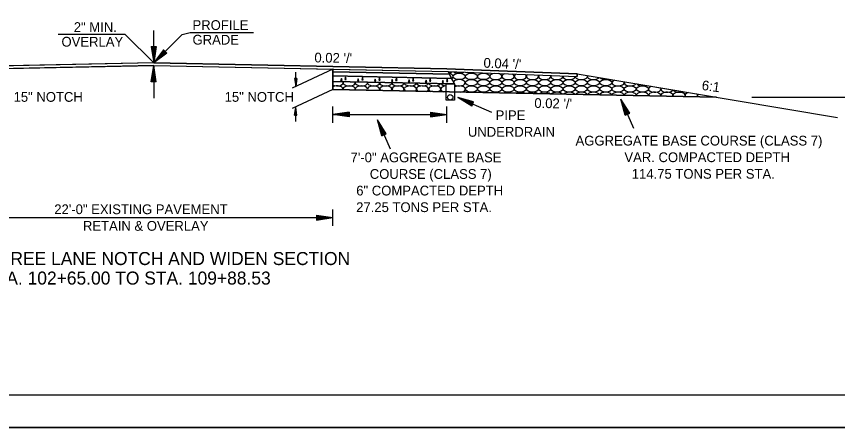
# Model space of a CAD drawing. Extents: x 1371763 to 1372860, y 385599 to 385872.
# Drawn here: x 1372352.1 to 1372402.6, y 385598.6 to 385623.8 of the extents above; entities that cross this region are included whole.
import ezdxf

# ---------------------------------------------------------------- set-up
doc = ezdxf.new("R2010")
doc.units = 0
for name, color, linetype in [('R_Border', 7, 'Continuous'), ('R_Draft', 7, 'Continuous'), ('R_No Plot', 7, 'Continuous')]:
    doc.layers.add(name, color=color, linetype=linetype)

msp = doc.modelspace()

# ---------------------------------------------------------------- linework, layer by layer
at = {"layer": 'R_Border'}
msp.add_line((1372457.298, 385600.577), (1372299.208, 385600.577), dxfattribs=at)
at = {"layer": 'R_Draft'}
for p, q in [((1372358.829, 385622.739), (1372354.703, 385622.739)), ((1372360.579, 385620.989), (1372358.829, 385622.739)), ((1372360.579, 385620.989), (1372360.579, 385622.989)), ((1372360.579, 385620.989), (1372362.329, 385622.739)), ((1372362.329, 385622.739), (1372362.829, 385622.864)), ((1372362.829, 385622.864), (1372366.715, 385622.864)), ((1372360.429, 385621.989), (1372360.579, 385620.989)), ((1372360.429, 385621.989), (1372360.729, 385621.989)), ((1372360.454, 385621.989), (1372360.579, 385621.156)), ((1372360.48, 385621.989), (1372360.579, 385621.328)), ((1372360.505, 385621.989), (1372360.579, 385621.494)), ((1372360.531, 385621.989), (1372360.579, 385621.664)), ((1372360.556, 385621.989), (1372360.579, 385621.831)), ((1372360.729, 385621.989), (1372360.579, 385620.989)), ((1372360.628, 385621.989), (1372360.579, 385621.664)), ((1372360.679, 385621.989), (1372360.579, 385621.328)), ((1372360.704, 385621.989), (1372360.579, 385621.156)), ((1372360.654, 385621.989), (1372360.579, 385621.494)), ((1372360.603, 385621.989), (1372360.579, 385621.831)), ((1372361.18, 385621.802), (1372360.579, 385620.989)), ((1372361.198, 385621.784), (1372360.697, 385621.107)), ((1372361.216, 385621.766), (1372360.819, 385621.228)), ((1372361.234, 385621.749), (1372360.937, 385621.346)), ((1372361.252, 385621.731), (1372361.057, 385621.466)), ((1372361.393, 385621.59), (1372361.18, 385621.802)), ((1372361.393, 385621.59), (1372360.579, 385620.989)), ((1372361.375, 385621.608), (1372360.697, 385621.107)), ((1372361.357, 385621.626), (1372360.819, 385621.228)), ((1372361.339, 385621.643), (1372360.937, 385621.346)), ((1372361.321, 385621.662), (1372361.057, 385621.466)), ((1372361.27, 385621.713), (1372361.175, 385621.584)), ((1372361.303, 385621.679), (1372361.175, 385621.584)), ((1372360.579, 385620.822), (1372342.495, 385620.46)), ((1372360.579, 385620.989), (1372342.579, 385620.629)), ((1372360.429, 385619.822), (1372360.579, 385620.822)), ((1372360.579, 385620.989), (1372378.579, 385620.629)), ((1372360.579, 385620.822), (1372378.664, 385620.46)), ((1372360.729, 385619.822), (1372360.579, 385620.822)), ((1372360.579, 385620.822), (1372360.579, 385618.822)), ((1372360.454, 385619.822), (1372360.579, 385620.655)), ((1372360.48, 385619.822), (1372360.579, 385620.483)), ((1372360.505, 385619.822), (1372360.579, 385620.317)), ((1372360.704, 385619.822), (1372360.579, 385620.655)), ((1372360.679, 385619.822), (1372360.579, 385620.483)), ((1372360.654, 385619.822), (1372360.579, 385620.317)), ((1372371.578, 385620.602), (1372369.091, 385619.43)), ((1372369.303, 385619.53), (1372369.303, 385620.43)), ((1372378.579, 385620.629), (1372386.579, 385620.309)), ((1372378.664, 385620.46), (1372378.748, 385620.292)), ((1372378.664, 385620.46), (1372386.579, 385620.144)), ((1372378.748, 385620.292), (1372378.874, 385620.04)), ((1372386.579, 385620.309), (1372402.579, 385617.642)), ((1372386.579, 385620.309), (1372386.579, 385620.144)), ((1372360.729, 385619.822), (1372360.429, 385619.822)), ((1372360.53, 385619.822), (1372360.579, 385620.147)), ((1372360.556, 385619.822), (1372360.579, 385619.98)), ((1372360.628, 385619.822), (1372360.579, 385620.147)), ((1372360.603, 385619.822), (1372360.579, 385619.98)), ((1372369.228, 385620.03), (1372369.303, 385619.53)), ((1372369.378, 385620.03), (1372369.228, 385620.03)), ((1372369.241, 385620.03), (1372369.303, 385619.614)), ((1372369.254, 385620.03), (1372369.303, 385619.7)), ((1372369.266, 385620.03), (1372369.303, 385619.783)), ((1372369.279, 385620.03), (1372369.303, 385619.868)), ((1372369.292, 385620.03), (1372369.303, 385619.951)), ((1372369.378, 385620.03), (1372369.303, 385619.53)), ((1372369.328, 385620.03), (1372369.303, 385619.868)), ((1372369.353, 385620.03), (1372369.303, 385619.7)), ((1372369.366, 385620.03), (1372369.303, 385619.614)), ((1372369.341, 385620.03), (1372369.303, 385619.783)), ((1372369.315, 385620.03), (1372369.303, 385619.951)), ((1372371.579, 385620.185), (1372378.874, 385620.04)), ((1372371.579, 385619.852), (1372379.042, 385619.703)), ((1372378.874, 385620.04), (1372379.042, 385619.703)), ((1372371.579, 385619.352), (1372369.091, 385618.18)), ((1372371.579, 385619.352), (1372395.148, 385618.881)), ((1372379.252, 385618.874), (1372381.318, 385617.964)), ((1372380.106, 385618.334), (1372379.252, 385618.874)), ((1372380.227, 385618.608), (1372379.252, 385618.874)), ((1372380.117, 385618.357), (1372379.404, 385618.806)), ((1372380.217, 385618.585), (1372379.404, 385618.806)), ((1372380.207, 385618.562), (1372379.562, 385618.737)), ((1372380.127, 385618.38), (1372379.562, 385618.737)), ((1372389.273, 385618.754), (1372390.052, 385616.98)), ((1372389.538, 385617.778), (1372389.273, 385618.754)), ((1372389.813, 385617.898), (1372389.273, 385618.754)), ((1372397.317, 385618.881), (1372406.175, 385618.881)), ((1372369.229, 385617.78), (1372369.304, 385618.28)), ((1372369.241, 385617.78), (1372369.304, 385618.197)), ((1372369.379, 385617.78), (1372369.304, 385618.28)), ((1372369.304, 385617.38), (1372369.304, 385618.28)), ((1372369.366, 385617.78), (1372369.304, 385618.197)), ((1372371.579, 385617.317), (1372371.579, 385618.317)), ((1372378.576, 385617.317), (1372378.576, 385618.317)), ((1372380.137, 385618.403), (1372379.714, 385618.67)), ((1372380.197, 385618.539), (1372379.714, 385618.67)), ((1372380.187, 385618.516), (1372379.869, 385618.602)), ((1372380.147, 385618.427), (1372379.869, 385618.602)), ((1372380.176, 385618.493), (1372380.022, 385618.535)), ((1372380.157, 385618.45), (1372380.022, 385618.535)), ((1372380.106, 385618.334), (1372380.227, 385618.608)), ((1372389.561, 385617.788), (1372389.34, 385618.601)), ((1372389.79, 385617.888), (1372389.34, 385618.601)), ((1372389.766, 385617.878), (1372389.41, 385618.443)), ((1372389.584, 385617.798), (1372389.41, 385618.443)), ((1372389.607, 385617.808), (1372389.476, 385618.291)), ((1372389.743, 385617.868), (1372389.476, 385618.291)), ((1372369.229, 385617.78), (1372369.379, 385617.78)), ((1372369.254, 385617.78), (1372369.304, 385618.111)), ((1372369.267, 385617.78), (1372369.304, 385618.028)), ((1372369.28, 385617.78), (1372369.304, 385617.943)), ((1372369.292, 385617.78), (1372369.304, 385617.859)), ((1372369.354, 385617.78), (1372369.304, 385618.111)), ((1372369.341, 385617.78), (1372369.304, 385618.028)), ((1372369.328, 385617.78), (1372369.304, 385617.943)), ((1372369.316, 385617.78), (1372369.304, 385617.859)), ((1372372.579, 385617.967), (1372371.579, 385617.817)), ((1372372.579, 385617.667), (1372371.579, 385617.817)), ((1372371.579, 385617.817), (1372378.576, 385617.817)), ((1372372.579, 385617.942), (1372371.746, 385617.817)), ((1372372.579, 385617.692), (1372371.746, 385617.817)), ((1372372.579, 385617.917), (1372371.918, 385617.817)), ((1372372.579, 385617.718), (1372371.918, 385617.817)), ((1372372.579, 385617.892), (1372372.085, 385617.817)), ((1372372.579, 385617.743), (1372372.085, 385617.817)), ((1372372.579, 385617.866), (1372372.254, 385617.817)), ((1372372.579, 385617.768), (1372372.254, 385617.817)), ((1372372.579, 385617.841), (1372372.421, 385617.817)), ((1372372.579, 385617.794), (1372372.421, 385617.817)), ((1372372.579, 385617.967), (1372372.579, 385617.667)), ((1372377.576, 385617.967), (1372378.576, 385617.817)), ((1372377.576, 385617.967), (1372377.576, 385617.667)), ((1372377.576, 385617.942), (1372378.409, 385617.817)), ((1372377.576, 385617.917), (1372378.237, 385617.817)), ((1372377.576, 385617.892), (1372378.07, 385617.817)), ((1372377.576, 385617.866), (1372377.901, 385617.817)), ((1372377.576, 385617.841), (1372377.734, 385617.817)), ((1372377.576, 385617.667), (1372378.576, 385617.817)), ((1372377.576, 385617.768), (1372377.901, 385617.817)), ((1372377.576, 385617.718), (1372378.237, 385617.817)), ((1372377.576, 385617.692), (1372378.409, 385617.817)), ((1372377.576, 385617.743), (1372378.07, 385617.817)), ((1372377.576, 385617.794), (1372377.734, 385617.817)), ((1372389.538, 385617.778), (1372389.813, 385617.898)), ((1372389.72, 385617.858), (1372389.545, 385618.136)), ((1372389.631, 385617.819), (1372389.545, 385618.136)), ((1372389.697, 385617.848), (1372389.612, 385617.983)), ((1372389.654, 385617.829), (1372389.612, 385617.983)), ((1372374.585, 385616.509), (1372374.32, 385617.485)), ((1372374.86, 385616.629), (1372374.32, 385617.485)), ((1372374.32, 385617.485), (1372375.099, 385615.711)), ((1372374.608, 385616.519), (1372374.387, 385617.332)), ((1372374.837, 385616.619), (1372374.387, 385617.332)), ((1372374.813, 385616.609), (1372374.456, 385617.174)), ((1372374.631, 385616.529), (1372374.456, 385617.174)), ((1372374.654, 385616.539), (1372374.523, 385617.022)), ((1372374.79, 385616.599), (1372374.523, 385617.022)), ((1372374.767, 385616.589), (1372374.592, 385616.867)), ((1372374.678, 385616.55), (1372374.592, 385616.867)), ((1372374.744, 385616.579), (1372374.659, 385616.714)), ((1372374.701, 385616.56), (1372374.659, 385616.714)), ((1372374.585, 385616.509), (1372374.86, 385616.629)), ((1372371.579, 385610.987), (1372371.579, 385611.987)), ((1372349.579, 385611.487), (1372371.579, 385611.487)), ((1372370.579, 385611.637), (1372371.579, 385611.487)), ((1372370.579, 385611.637), (1372370.579, 385611.337)), ((1372370.579, 385611.612), (1372371.412, 385611.487)), ((1372370.579, 385611.586), (1372371.24, 385611.487)), ((1372370.579, 385611.561), (1372371.074, 385611.487)), ((1372370.579, 385611.535), (1372370.904, 385611.487)), ((1372370.579, 385611.51), (1372370.737, 385611.487)), ((1372370.579, 385611.337), (1372371.579, 385611.487)), ((1372370.579, 385611.438), (1372370.904, 385611.487)), ((1372370.579, 385611.387), (1372371.24, 385611.487)), ((1372370.579, 385611.362), (1372371.412, 385611.487)), ((1372370.579, 385611.412), (1372371.074, 385611.487)), ((1372370.579, 385611.463), (1372370.737, 385611.487))]:
    msp.add_line(p, q, dxfattribs=at)
for points in [[(1372360.579, 385620.989), (1372342.579, 385620.629), (1372334.579, 385620.309), (1372334.579, 385620.144), (1372342.495, 385620.46), (1372349.58, 385620.602), (1372360.579, 385620.822), (1372371.578, 385620.602), (1372378.664, 385620.46), (1372386.579, 385620.144), (1372386.579, 385620.309), (1372378.579, 385620.629)], [(1372371.578, 385620.602), (1372378.664, 385620.46), (1372378.748, 385620.292), (1372371.579, 385620.435)], [(1372371.579, 385619.352), (1372371.579, 385619.852), (1372379.042, 385619.703), (1372378.874, 385620.04), (1372378.748, 385620.292), (1372378.664, 385620.46), (1372386.579, 385620.144), (1372386.579, 385620.309), (1372395.148, 385618.881)], [(1372371.579, 385620.185), (1372371.579, 385620.435), (1372378.748, 385620.292), (1372378.874, 385620.04)], [(1372371.579, 385620.185), (1372378.874, 385620.04), (1372379.042, 385619.703), (1372371.579, 385619.852)], [(1372379.042, 385619.703), (1372379.042, 385618.705), (1372378.539, 385618.705), (1372378.539, 385619.703)]]:
    msp.add_lwpolyline(points, close=True, dxfattribs=at)
for points in [[(1372371.578, 385620.602), (1372371.579, 385620.435), (1372371.579, 385620.185), (1372371.579, 385619.852), (1372371.579, 385619.352)], [(1372371.579, 385620.435), (1372378.748, 385620.292)], [(1372372.105, 385620.041), (1372372.057, 385619.908), (1372372.145, 385619.912), (1372372.105, 385620.041)], [(1372372.364, 385620.107), (1372372.316, 385619.974), (1372372.404, 385619.978), (1372372.364, 385620.107)], [(1372373.145, 385620.02), (1372373.096, 385619.887), (1372373.184, 385619.891), (1372373.145, 385620.02)], [(1372373.404, 385620.086), (1372373.355, 385619.953), (1372373.443, 385619.957), (1372373.404, 385620.086)], [(1372374.185, 385619.999), (1372374.136, 385619.867), (1372374.224, 385619.87), (1372374.185, 385619.999)], [(1372374.444, 385620.065), (1372374.395, 385619.933), (1372374.483, 385619.936), (1372374.444, 385620.065)], [(1372375.225, 385619.979), (1372375.176, 385619.846), (1372375.264, 385619.849), (1372375.225, 385619.979)], [(1372375.484, 385620.045), (1372375.435, 385619.912), (1372375.523, 385619.915), (1372375.484, 385620.045)], [(1372376.264, 385619.958), (1372376.216, 385619.825), (1372376.304, 385619.829), (1372376.264, 385619.958)], [(1372376.523, 385620.024), (1372376.475, 385619.891), (1372376.563, 385619.895), (1372376.523, 385620.024)], [(1372377.304, 385619.937), (1372377.256, 385619.804), (1372377.344, 385619.808), (1372377.304, 385619.937)], [(1372377.563, 385620.003), (1372377.515, 385619.87), (1372377.603, 385619.874), (1372377.563, 385620.003)], [(1372378.344, 385619.916), (1372378.296, 385619.783), (1372378.384, 385619.787), (1372378.344, 385619.916)], [(1372378.603, 385619.982), (1372378.555, 385619.849), (1372378.643, 385619.853), (1372378.603, 385619.982)]]:
    msp.add_lwpolyline(points, dxfattribs=at)
msp.add_circle((1372378.791, 385618.872), 0.167, dxfattribs=at)
for centre, start_param, end_param in [((1372378.587, 385620.547), 5.051096, 5.763875), ((1372378.587, 385620.158), 0.74402, 1.197348), ((1372378.587, 385620.158), 5.592596, 7.027205), ((1372379.338, 385620.547), 3.685644, 5.585033), ((1372380.088, 385620.547), 3.891507, 5.37917), ((1372380.838, 385620.547), 4.161511, 5.109166), ((1372381.588, 385620.158), 1.810379, 6.670932), ((1372381.588, 385620.158), 0.387746, 1.177112), ((1372382.339, 385620.158), 2.143322, 6.592146), ((1372382.339, 385620.158), 0.308961, 0.84417), ((1372383.089, 385620.158), 2.366927, 6.51554), ((1372383.089, 385620.158), 0.232354, 0.620564), ((1372383.839, 385620.158), 2.554238, 6.44052), ((1372383.839, 385620.158), 0.157335, 0.433254), ((1372384.589, 385620.158), 2.723473, 6.366593), ((1372386.84, 385620.158), 2.278485, 2.33986), ((1372371.835, 385619.77), 3.96261, 6.65316), ((1372372.585, 385619.77), 2.777136, 6.570444), ((1372373.335, 385619.77), 2.857595, 6.489984), ((1372374.086, 385619.77), 2.936461, 6.411118), ((1372374.836, 385619.77), 3.014293, 6.333287), ((1372375.586, 385619.77), 3.091588, 6.255992), ((1372376.336, 385619.77), 3.168815, 6.178765), ((1372377.087, 385619.77), 3.246438, 6.101142), ((1372377.837, 385619.77), 3.324943, 6.022637), ((1372378.587, 385619.77), 3.404868, 4.583286), ((1372379.338, 385619.77), 3.80645, 9.119957), ((1372385.34, 385620.158), 2.883001, 6.293319), ((1372384.589, 385620.158), 0.083407, 0.264018), ((1372386.09, 385620.158), 3.037942, 6.232735), ((1372385.34, 385620.158), 0.010134, 0.104491), ((1372386.84, 385620.158), 3.19224, 6.523589), ((1372387.59, 385620.158), 2.918865, 5.883208), ((1372388.341, 385620.158), 3.607321, 5.194752), ((1372389.091, 385619.77), 2.199247, 6.602826), ((1372389.841, 385619.77), 2.852988, 5.949086), ((1372371.835, 385619.381), 6.067704, 8.604148), ((1372372.585, 385619.381), 5.988661, 9.642104), ((1372373.335, 385619.381), 5.907944, 9.722821), ((1372374.086, 385619.381), 5.824873, 9.805892), ((1372374.836, 385619.381), 5.738592, 9.892174), ((1372375.586, 385619.381), 5.647958, 9.982807), ((1372376.336, 385619.381), 5.551342, 10.079423), ((1372377.087, 385619.381), 5.446223, 10.184542), ((1372377.837, 385619.381), 5.328222, 10.302543), ((1372378.587, 385619.381), 1.6999, 4.159359), ((1372379.338, 385619.381), 2.178393, 2.476736), ((1372379.338, 385619.381), 4.998472, 8.461578), ((1372382.339, 385618.993), 0.797512, 2.266882), ((1372390.592, 385619.77), 3.518815, 5.283258), ((1372391.342, 385619.381), 2.115117, 6.31057), ((1372391.342, 385618.993), 0.337275, 3.288156), ((1372391.342, 385619.381), 0.027385, 0.403771), ((1372392.092, 385619.381), 2.787209, 6.014865), ((1372392.842, 385619.381), 3.436349, 5.365724), ((1372380.088, 385618.993), 1.301815, 1.762579), ((1372380.838, 385618.993), 1.072981, 1.991414), ((1372381.588, 385618.993), 0.921452, 2.142942), ((1372383.089, 385618.993), 0.688711, 2.375683), ((1372383.839, 385618.993), 0.589594, 2.4748), ((1372384.589, 385618.993), 0.497173, 2.567222), ((1372385.34, 385618.993), 0.409581, 2.654814), ((1372386.09, 385618.993), 0.325542, 2.738853), ((1372386.84, 385618.993), 0.24412, 2.820275), ((1372387.59, 385618.993), 0.164585, 2.89981), ((1372388.341, 385618.993), 0.086335, 2.978059), ((1372389.091, 385618.993), 0.008849, 3.055545), ((1372389.841, 385618.993), 0.853185, 3.132747), ((1372389.841, 385618.993), 6.214833, 7.136371), ((1372390.592, 385618.993), 0.568033, 3.210126), ((1372390.592, 385618.993), 6.137454, 6.851218), ((1372392.092, 385618.993), 0.129417, 3.367348), ((1372391.342, 385618.993), 6.059423, 6.620461), ((1372392.092, 385618.993), 5.980232, 6.412602), ((1372392.842, 385618.993), 3.013817, 3.448278), ((1372392.842, 385618.993), 5.899301, 9.297002), ((1372393.593, 385618.993), 2.024311, 3.531644), ((1372393.593, 385618.993), 0.342438, 0.494577), ((1372393.593, 385618.993), 5.815936, 6.625624), ((1372394.343, 385618.993), 2.721243, 3.618325), ((1372394.343, 385618.993), 5.729255, 6.080831), ((1372395.093, 385618.993), 3.35836, 3.709502)]:
    msp.add_ellipse(centre, major_axis=(0.375, 0), ratio=0.517889, start_param=start_param, end_param=end_param, dxfattribs=at)
for centre in [(1372379.338, 385620.158), (1372380.088, 385620.158), (1372380.838, 385620.158), (1372380.088, 385619.77), (1372380.838, 385619.77), (1372381.588, 385619.77), (1372382.339, 385619.77), (1372383.089, 385619.77), (1372383.839, 385619.77), (1372384.589, 385619.77), (1372385.34, 385619.77), (1372386.09, 385619.77), (1372386.84, 385619.77), (1372387.59, 385619.77), (1372388.341, 385619.77), (1372380.088, 385619.381), (1372380.838, 385619.381), (1372381.588, 385619.381), (1372382.339, 385619.381), (1372383.089, 385619.381), (1372383.839, 385619.381), (1372384.589, 385619.381), (1372385.34, 385619.381), (1372386.09, 385619.381), (1372386.84, 385619.381), (1372387.59, 385619.381), (1372388.341, 385619.381), (1372389.091, 385619.381), (1372389.841, 385619.381), (1372390.592, 385619.381)]:
    msp.add_ellipse(centre, major_axis=(0.375, 0), ratio=0.517889, dxfattribs=at)
at = {"layer": 'R_No Plot'}
msp.add_line((1372293.007, 385598.587), (1372459.674, 385598.587), dxfattribs=at)
for points in [[(1372293.004, 385705.254), (1372459.674, 385705.254), (1372459.674, 385598.585), (1372293.004, 385598.585)], [(1372416.168, 385703.307), (1372425.978, 385703.307), (1372425.978, 385698.367), (1372434.034, 385698.367), (1372445.634, 385698.367), (1372445.634, 385682.032), (1372457.238, 385682.032), (1372457.298, 385600.577), (1372299.208, 385600.577), (1372299.208, 385703.307)]]:
    msp.add_lwpolyline(points, close=True, dxfattribs=at)

# ---------------------------------------------------------------- texts
at = {"layer": 'R_Draft'}
for s, height, p in [('2" MIN.', 0.6, (1372355.672, 385622.889)), ('PROFILE', 0.6, (1372362.963, 385623.014)), ('OVERLAY', 0.6, (1372354.917, 385621.989)), ('GRADE', 0.6, (1372362.963, 385622.114)), ('15" NOTCH', 0.6, (1372351.975, 385618.6)), ('15" NOTCH', 0.6, (1372364.937, 385618.6)), ('HWY. 72 - THREE LANE NOTCH AND WIDEN SECTION', 0.8, (1372345.124, 385608.571)), ('STA. 102+65.00 TO STA. 109+88.53', 0.8, (1372350.16, 385607.371))]:
    msp.add_text(s, height=height, dxfattribs=at).set_placement(p)
for s, rotation, p in [("0.02 '/'", 359.0147, (1372370.445, 385621.021)), ("0.04 '/'", 357.6223, (1372380.823, 385620.701)), ('6:1', 352.2846, (1372394.209, 385619.333)), ("0.02 '/'", 359.0147, (1372383.951, 385618.226)), ('PIPE', 360, (1372381.577, 385617.474)), ('UNDERDRAIN', 360, (1372379.873, 385616.454)), ('AGGREGATE BASE COURSE (CLASS 7)', 360, (1372386.485, 385615.914)), ('7\'-0" AGGREGATE BASE ', 360, (1372372.668, 385614.885)), ('VAR. COMPACTED DEPTH', 360, (1372389.485, 385614.894)), ('COURSE (CLASS 7)', 360, (1372373.849, 385613.865)), ('114.75 TONS PER STA.', 360, (1372389.939, 385613.874)), ('6" COMPACTED DEPTH', 360, (1372373.018, 385612.845)), ('22\'-0" EXISTING PAVEMENT', 360, (1372354.473, 385611.697)), ('27.25 TONS PER STA.', 360, (1372373.013, 385611.825)), ('RETAIN & OVERLAY', 360, (1372356.233, 385610.677))]:
    msp.add_text(s, height=0.6, rotation=rotation, dxfattribs=at).set_placement(p)

doc.saveas('drawing.dxf')
